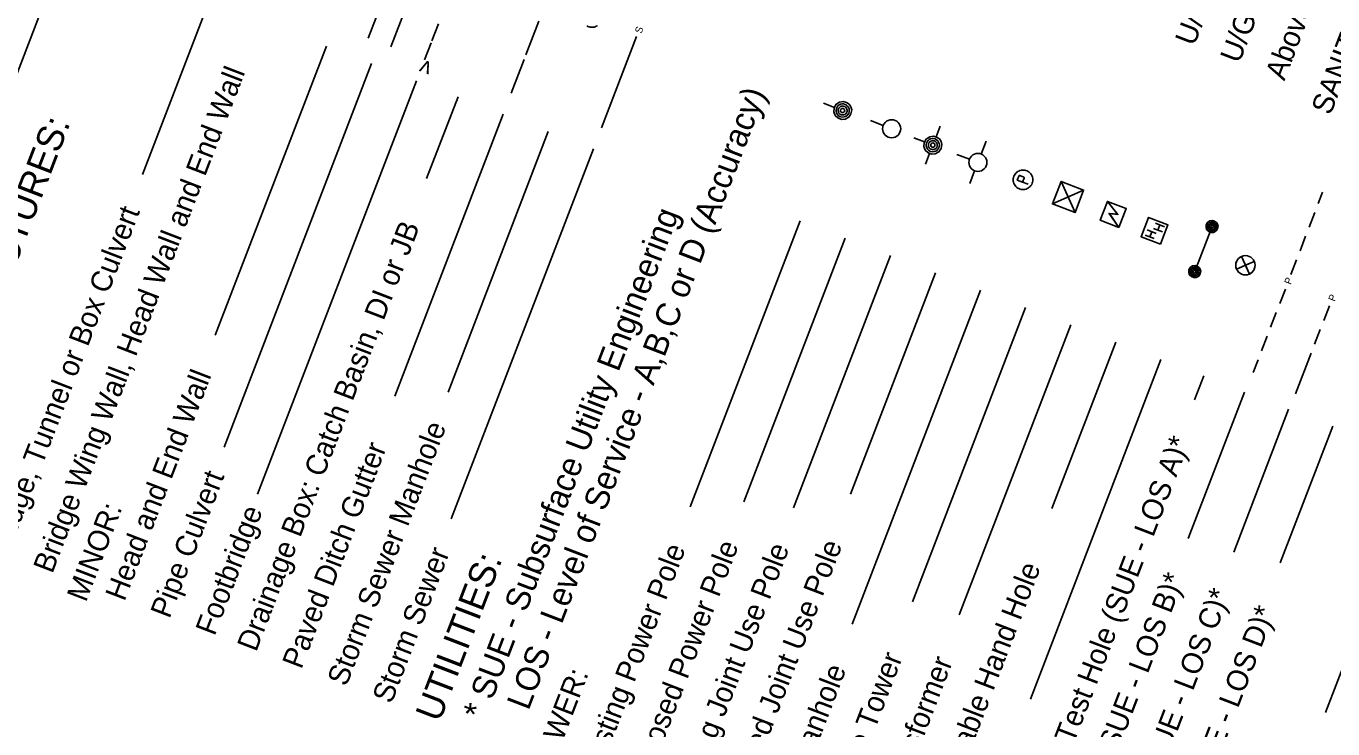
# Model space of a CAD drawing. Extents: x 1015221 to 1064345, y 619216 to 647967.
# Drawn here: x 1047324 to 1051569, y 630539 to 632823 of the extents above; entities that cross this region are included whole.
import ezdxf

# ---------------------------------------------------------------- set-up
doc = ezdxf.new("R2010")
doc.units = 0
doc.layers.add('Default', color=7, linetype='Continuous')

msp = doc.modelspace()

# ---------------------------------------------------------------- linework, layer by layer
at = {"layer": 'Default'}
for p, q in [((1048435, 632784.1), (1048667.1, 633388.3)), ((1048508.2, 632756), (1048740.4, 633360.2)), ((1047465.1, 633114.8), (1046888.4, 631613.8)), ((1047918.1, 632904.5), (1047701.5, 632340.8)), ((1048642, 632776), (1048663.1, 632830.9)), ((1048947.4, 632730.1), (1048989.6, 632840)), ((1049192.6, 632493), (1049306.6, 632789.8)), ((1048298.9, 632758.2), (1047937.9, 631818.5)), ((1048618.1, 632713.7), (1048639.2, 632768.7)), ((1048445.4, 632701.9), (1047966.5, 631455.4)), ((1048899.6, 632605.6), (1048941.8, 632715.4)), ((1048591.9, 632645.6), (1048075.6, 631301.8)), ((1048726.9, 632593.8), (1048624.8, 632327.9)), ((1049949.3, 632559.5), (1049914.1, 632573)), ((1048873.4, 632537.5), (1048521.1, 631620.6)), ((1050107.9, 632500.4), (1050066.7, 632516.2)), ((1049019.9, 632481.2), (1048694.4, 631634)), ((1050279.7, 632463.6), (1050293.2, 632498.7)), ((1050242.2, 632447), (1050207.1, 632460.5)), ((1050426.2, 632407.8), (1050442.1, 632449)), ((1049166.4, 632424.9), (1048704.3, 631222.3)), ((1050258.9, 632409.5), (1050245.4, 632374.4)), ((1050388.2, 632390.9), (1050347, 632406.7)), ((1050405.1, 632352.9), (1050389.3, 632311.7)), ((1050551.9, 632337.5), (1050564.5, 632332.7)), ((1050566, 632329.4), (1050560.8, 632316.1)), ((1050686.1, 632318.6), (1050731.2, 632217.3)), ((1050759.3, 632290.5), (1050658, 632245.5)), ((1051521.3, 632246.6), (1051535.6, 632284)), ((1049838.4, 632190.2), (1049481.4, 631261)), ((1050992.3, 632183), (1051021.8, 632171.6)), ((1051000.8, 632160.3), (1051007.3, 632177.2)), ((1051491.7, 632169.7), (1051510, 632217.3)), ((1049984.9, 632133.9), (1049655.7, 631277.1)), ((1050958.9, 632144.1), (1050988.4, 632132.8)), ((1050965.3, 632161), (1050994.9, 632149.6)), ((1050973.9, 632138.3), (1050980.4, 632155.2)), ((1050985.8, 632166.1), (1051015.3, 632154.8)), ((1051120.1, 632025.6), (1051176.3, 632172.1)), ((1051462.2, 632092.8), (1051480.5, 632140.4)), ((1050131.4, 632077.6), (1049816.5, 631257.9)), ((1051432.6, 632015.9), (1051450.9, 632063.5)), ((1050277.9, 632021.3), (1050001.4, 631301.9)), ((1050424.3, 631965), (1050007.4, 630879.9)), ((1051396.3, 631921.4), (1051414.6, 631969)), ((1050570.8, 631908.8), (1050203.1, 630951.7)), ((1051366.8, 631844.5), (1051385.1, 631892.1)), ((1051539.2, 631866.5), (1051557.5, 631914.1)), ((1050717.3, 631852.5), (1050355.3, 630910.3)), ((1051509.7, 631789.6), (1051528, 631837.2)), ((1050863.8, 631796.2), (1050655.9, 631255)), ((1051337.2, 631767.6), (1051355.5, 631815.2)), ((1051447.7, 631628.3), (1051498.4, 631760.3)), ((1051010.3, 631739.9), (1050586.2, 630636.2)), ((1051310.5, 631698), (1051326, 631738.3)), ((1051149.3, 631686.5), (1051119.3, 631608.6)), ((1051281.5, 631633.4), (1051098.9, 631157.9)), ((1051425.2, 631578.2), (1051246.9, 631114)), ((1051568.9, 631523), (1051398.1, 631078.5)), ((1051859.3, 631411.4), (1051544.5, 630591.9))]:
    msp.add_line(p, q, dxfattribs=at)
for points in [[(1049145.5, 632824.5), (1049148.9, 632822.7), (1049152.7, 632821.2), (1049156.5, 632820.3), (1049160.6, 632819.8), (1049164.4, 632819.7), (1049168.5, 632820.3), (1049172.2, 632821.4), (1049176, 632822.9), (1049179.5, 632824.8)], [(1049984, 632569.1), (1049978.9, 632570.5), (1049974, 632570.5), (1049969.2, 632569.3), (1049964.7, 632567.2), (1049961, 632564.3), (1049958.1, 632559.8), (1049955.9, 632555.7), (1049955.1, 632550.4), (1049955.1, 632545.5), (1049956.5, 632541.2), (1049959.1, 632536.5), (1049962, 632532.9), (1049966.5, 632529.9), (1049970.8, 632528.3), (1049976.1, 632527.5), (1049980.7, 632528.2), (1049985.7, 632530), (1049989.7, 632532.2), (1049993, 632535.9), (1049995.9, 632540.3), (1049997, 632544.9), (1049997.8, 632550.2), (1049997.1, 632554.8), (1049995.1, 632559.3), (1049992.4, 632563.4), (1049988.7, 632566.7), (1049984, 632569.1)], [(1049981.5, 632562.6), (1049977.5, 632563.6), (1049973.1, 632563.4), (1049969.4, 632561.7), (1049966, 632559.3), (1049963.6, 632556.5), (1049962, 632552.2), (1049961.8, 632548.5), (1049962.7, 632544.4), (1049964.4, 632540.7), (1049967.5, 632537.6), (1049971.1, 632535.6), (1049975.1, 632534.7), (1049979.5, 632534.9), (1049983.3, 632536.5), (1049986.7, 632538.9), (1049989, 632541.8), (1049990.7, 632546.1), (1049990.8, 632549.8), (1049989.9, 632553.8), (1049988.2, 632557.6), (1049985.1, 632560.6), (1049981.5, 632562.6)], [(1049978.8, 632555.6), (1049975.9, 632556.1), (1049973.1, 632555.3), (1049971.2, 632553.6), (1049969.6, 632551.1), (1049969.7, 632548), (1049970.5, 632545.2), (1049972.7, 632543.1), (1049974.9, 632542.2), (1049978, 632542.3), (1049980.5, 632543.8), (1049982.6, 632546.1), (1049983.1, 632549), (1049982.8, 632551.6), (1049981.3, 632554), (1049978.8, 632555.6)], [(1050277, 632456.6), (1050271.9, 632457.9), (1050267, 632457.9), (1050262.1, 632456.7), (1050257.6, 632454.7), (1050254, 632451.7), (1050251.1, 632447.3), (1050248.9, 632443.2), (1050248.1, 632437.9), (1050248, 632432.9), (1050249.5, 632428.7), (1050252, 632424), (1050255, 632420.3), (1050259.4, 632417.4), (1050263.8, 632415.7), (1050269, 632414.9), (1050273.7, 632415.7), (1050278.7, 632417.4), (1050282.6, 632419.6), (1050285.9, 632423.3), (1050288.9, 632427.8), (1050290, 632432.3), (1050290.8, 632437.6), (1050290.1, 632442.2), (1050288.1, 632446.7), (1050285.3, 632450.9), (1050281.6, 632454.2), (1050277, 632456.6)], [(1050274.5, 632450.1), (1050270.5, 632451), (1050266.1, 632450.8), (1050262.3, 632449.2), (1050258.9, 632446.8), (1050256.6, 632443.9), (1050254.9, 632439.6), (1050254.8, 632435.9), (1050255.7, 632431.9), (1050257.4, 632428.1), (1050260.5, 632425), (1050264.1, 632423.1), (1050268.1, 632422.1), (1050272.5, 632422.3), (1050276.2, 632424), (1050279.6, 632426.4), (1050282, 632429.2), (1050283.6, 632433.5), (1050283.8, 632437.2), (1050282.9, 632441.3), (1050281.2, 632445), (1050278.1, 632448.1), (1050274.5, 632450.1)], [(1050271.8, 632443.1), (1050268.9, 632443.6), (1050266.1, 632442.8), (1050264.2, 632441), (1050262.6, 632438.5), (1050262.6, 632435.4), (1050263.4, 632432.6), (1050265.7, 632430.5), (1050267.9, 632429.7), (1050271, 632429.7), (1050273.5, 632431.3), (1050275.6, 632433.5), (1050276.1, 632436.4), (1050275.8, 632439), (1050274.3, 632441.5), (1050271.8, 632443.1)], [(1050532.5, 632335.4), (1050531.3, 632331.5), (1050530.6, 632327.7), (1050530.5, 632323.7), (1050530.8, 632319.7), (1050531.6, 632315.9), (1050532.8, 632312.1), (1050534.7, 632308.4), (1050536.7, 632305.2), (1050539.3, 632302), (1050542.4, 632299.4), (1050545.6, 632297.1), (1050549, 632295.2), (1050552.8, 632293.8), (1050556.6, 632292.9), (1050560.7, 632292.4), (1050564.5, 632292.3), (1050568.6, 632292.9), (1050572.3, 632293.9), (1050576.1, 632295.5), (1050579.6, 632297.4), (1050582.7, 632299.8), (1050585.6, 632302.5), (1050588.2, 632305.6), (1050590.4, 632309.1), (1050592, 632312.6), (1050593.2, 632316.5), (1050593.9, 632320.3), (1050594.1, 632324.4), (1050593.7, 632328.3), (1050593, 632332.1), (1050591.7, 632335.9), (1050589.8, 632339.6), (1050587.8, 632342.9), (1050585.2, 632346), (1050582.1, 632348.6), (1050578.9, 632350.9), (1050575.5, 632352.8), (1050571.7, 632354.2), (1050567.9, 632355.1), (1050563.8, 632355.6), (1050560, 632355.7), (1050555.9, 632355.1), (1050552.2, 632354.1), (1050548.4, 632352.5), (1050544.9, 632350.6), (1050541.8, 632348.2), (1050538.9, 632345.6), (1050536.3, 632342.4), (1050534.1, 632338.9), (1050532.5, 632335.4)], [(1050578.5, 632309.3), (1050560.8, 632316.1), (1050543.5, 632322.8), (1050548.6, 632336.1)], [(1050548.6, 632336.1), (1050549.2, 632336.9), (1050550, 632337.5), (1050550.9, 632337.7), (1050551.9, 632337.5)], [(1050564.5, 632332.7), (1050565.4, 632332.1), (1050565.9, 632331.3), (1050566.1, 632330.5), (1050566, 632329.4)], [(1050759.3, 632290.5), (1050731.2, 632217.3), (1050658, 632245.5), (1050686.1, 632318.6), (1050759.3, 632290.5), (1050731.2, 632217.3), (1050658, 632245.5), (1050686.1, 632318.6), (1050759.3, 632290.5)], [(1050874, 632169.2), (1050897.5, 632230.2), (1050836.4, 632253.7), (1050813, 632192.7), (1050874, 632169.2)], [(1050874, 632169.2), (1050843.7, 632213.9), (1050868.9, 632212.3), (1050836.4, 632253.7)], [(1050874, 632169.2), (1050842.1, 632214.8), (1050870.5, 632211.4), (1050836.4, 632253.7)], [(1051009.1, 632114.4), (1051033.3, 632177.5), (1050970.2, 632201.7), (1050946, 632138.6), (1051009.1, 632114.4)], [(1051181.5, 632185.5), (1051178.1, 632186.4), (1051174.8, 632186.4), (1051171.6, 632185.5), (1051168.6, 632184.2), (1051166.2, 632182.3), (1051164.2, 632179.3), (1051162.7, 632176.5), (1051162.2, 632173), (1051162.2, 632169.7), (1051163.1, 632166.9), (1051164.8, 632163.7), (1051166.8, 632161.3), (1051169.8, 632159.3), (1051172.6, 632158.2), (1051176.2, 632157.7), (1051179.3, 632158.2), (1051182.6, 632159.4), (1051185.2, 632160.9), (1051187.4, 632163.3), (1051189.4, 632166.3), (1051190.1, 632169.3), (1051190.7, 632172.8), (1051190.2, 632175.9), (1051188.9, 632178.9), (1051187, 632181.7), (1051184.6, 632183.9), (1051181.5, 632185.5)], [(1051179.8, 632181.1), (1051177.1, 632181.8), (1051174.2, 632181.6), (1051171.7, 632180.5), (1051169.4, 632178.9), (1051167.9, 632177), (1051166.8, 632174.2), (1051166.7, 632171.7), (1051167.3, 632169), (1051168.4, 632166.5), (1051170.5, 632164.5), (1051172.9, 632163.1), (1051175.5, 632162.5), (1051178.5, 632162.6), (1051181, 632163.7), (1051183.2, 632165.3), (1051184.8, 632167.2), (1051185.9, 632170.1), (1051186, 632172.6), (1051185.4, 632175.3), (1051184.3, 632177.8), (1051182.2, 632179.8), (1051179.8, 632181.1)], [(1051178, 632176.5), (1051176.1, 632176.8), (1051174.2, 632176.3), (1051172.9, 632175.1), (1051171.9, 632173.4), (1051171.9, 632171.4), (1051172.4, 632169.5), (1051173.9, 632168.1), (1051175.4, 632167.5), (1051177.5, 632167.6), (1051179.1, 632168.6), (1051180.5, 632170.1), (1051180.9, 632172.1), (1051180.7, 632173.8), (1051179.7, 632175.4), (1051178, 632176.5)], [(1051272.1, 632074.8), (1051297.6, 632017.5), (1051284.8, 632046.2), (1051256.2, 632033.4), (1051313.5, 632058.9)], [(1051256.2, 632033.4), (1051284.8, 632046.2), (1051272.1, 632074.8)], [(1051313.5, 632058.9), (1051284.8, 632046.2), (1051297.6, 632017.5)], [(1051125.2, 632039), (1051121.8, 632039.9), (1051118.5, 632039.9), (1051115.3, 632039.1), (1051112.3, 632037.7), (1051109.9, 632035.8), (1051107.9, 632032.8), (1051106.4, 632030), (1051105.9, 632026.5), (1051105.9, 632023.2), (1051106.9, 632020.4), (1051108.6, 632017.3), (1051110.5, 632014.8), (1051113.5, 632012.9), (1051116.4, 632011.8), (1051119.9, 632011.2), (1051123, 632011.7), (1051126.3, 632012.9), (1051129, 632014.4), (1051131.1, 632016.8), (1051133.1, 632019.8), (1051133.9, 632022.8), (1051134.4, 632026.3), (1051133.9, 632029.4), (1051132.6, 632032.4), (1051130.7, 632035.2), (1051128.3, 632037.4), (1051125.2, 632039)], [(1051123.5, 632034.7), (1051120.9, 632035.3), (1051117.9, 632035.2), (1051115.4, 632034), (1051113.1, 632032.4), (1051111.6, 632030.6), (1051110.5, 632027.7), (1051110.4, 632025.2), (1051111, 632022.5), (1051112.1, 632020), (1051114.2, 632018), (1051116.6, 632016.6), (1051119.3, 632016), (1051122.2, 632016.1), (1051124.7, 632017.3), (1051127, 632018.9), (1051128.5, 632020.7), (1051129.6, 632023.6), (1051129.7, 632026.1), (1051129.1, 632028.8), (1051128, 632031.3), (1051125.9, 632033.3), (1051123.5, 632034.7)], [(1051121.7, 632030), (1051119.8, 632030.3), (1051117.9, 632029.8), (1051116.6, 632028.6), (1051115.6, 632027), (1051115.6, 632024.9), (1051116.1, 632023), (1051117.7, 632021.6), (1051119.1, 632021), (1051121.2, 632021.1), (1051122.8, 632022.1), (1051124.2, 632023.6), (1051124.6, 632025.6), (1051124.4, 632027.3), (1051123.4, 632028.9), (1051121.7, 632030)]]:
    msp.add_lwpolyline(points, dxfattribs=at)
for points in [[(1050003.4, 632538.7), (1050005.6, 632550.9), (1050003.1, 632560.6), (1049997.8, 632569.4), (1049988.3, 632575.5), (1049978.2, 632578.2), (1049966.4, 632576.5), (1049954.1, 632568.8), (1049948.2, 632556.8), (1049947.3, 632544.8), (1049951.6, 632533.2), (1049960.2, 632524.9), (1049972.1, 632520.4), (1049984, 632520.7), (1049995.9, 632527.3)], [(1050296.3, 632426.2), (1050298.5, 632438.4), (1050296, 632448), (1050290.7, 632456.9), (1050281.3, 632463), (1050271.1, 632465.6), (1050259.3, 632464), (1050247.1, 632456.3), (1050241.2, 632444.3), (1050240.3, 632432.2), (1050244.6, 632420.6), (1050253.2, 632412.4), (1050265.1, 632407.8), (1050277, 632408.2), (1050288.9, 632414.8)], [(1051194.4, 632165.2), (1051195.8, 632173.3), (1051194.2, 632179.8), (1051190.6, 632185.7), (1051184.3, 632189.7), (1051177.6, 632191.5), (1051169.7, 632190.4), (1051161.5, 632185.3), (1051157.6, 632177.3), (1051157, 632169.2), (1051159.8, 632161.5), (1051165.6, 632156), (1051173.5, 632153), (1051181.5, 632153.2), (1051189.4, 632157.6)], [(1051138.1, 632018.7), (1051139.5, 632026.8), (1051137.9, 632033.3), (1051134.3, 632039.2), (1051128.1, 632043.3), (1051121.3, 632045), (1051113.4, 632043.9), (1051105.2, 632038.8), (1051101.3, 632030.8), (1051100.7, 632022.7), (1051103.6, 632015), (1051109.3, 632009.5), (1051117.2, 632006.5), (1051125.2, 632006.7), (1051133.1, 632011.1)]]:
    msp.add_lwpolyline(points, close=True, dxfattribs=at)
for centre, radius in [((1050135.4, 632489.8), 29.4), ((1050415.8, 632380.3), 29.4), ((1051284.8, 632046.2), 31.4)]:
    msp.add_circle(centre, radius, dxfattribs=at)
for start, end in [(113.983, 203.983), (293.983, 23.983)]:
    msp.add_arc((1051284.8, 632046.2), 31.4, start, end, dxfattribs=at)

# ---------------------------------------------------------------- texts
for s, height, rotation, p in [('U/G Gas Line (SUE - LOS C)*', 68.654, 68.983, (1051118.3, 632756)), ('U/G Gas Line (SUE - LOS D)*', 68.654, 68.983, (1051264.8, 632699.7)), ('Above Ground Gas Line', 68.654, 68.983, (1051411.3, 632643.4)), ('SANITARY SEWER:', 68.654, 68.983, (1051561, 632531.1)), ('S', 23.5, 68.983, (1049322.1, 632797.3)), ('Bridge Wing Wall, Head Wall and End Wall', 68.654, 68.983, (1047408.6, 631041.3)), ('v', 51.8, 158.7422, (1048645.4, 632703.1)), ('LOS - Level of Service - A,B,C or D (Accuracy) ', 77.677, 68.983, (1048955.7, 630596.5)), ('EXISTING STRUCTURES:', 86.308, 68.983, (1046969.2, 631210.1)), ('Bridge, Tunnel or Box Culvert', 68.654, 68.983, (1047262.1, 631097.5)), ('* SUE - Subsurface Utility Engineering', 77.677, 68.983, (1048812.8, 630565.1)), ('Drainage Box: Catch Basin, DI or JB', 68.654, 68.983, (1048070.9, 630786.9)), ('P', 23.5, 68.983, (1051432.1, 631981.6)), ('P', 23.5, 68.983, (1051575, 631926.7)), ('Head and End Wall', 68.654, 68.983, (1047642.9, 630951.2)), ('Storm Sewer Manhole', 68.654, 68.983, (1048363.9, 630674.3)), ('Paved Ditch Gutter', 68.654, 68.983, (1048217.5, 630730.6)), ('U/G Power Line Test Hole (SUE - LOS A)*', 68.654, 68.983, (1050485.4, 629859.5)), ('Pipe Culvert', 68.654, 68.983, (1047789.3, 630895)), ('MINOR:', 68.65, 68.983, (1047517.9, 630948.6)), ('Footbridge', 68.65, 68.983, (1047935.8, 630838.8)), ('Storm Sewer', 68.654, 68.983, (1048510.4, 630618)), ('Existing Power Pole', 68.654, 68.983, (1049174.5, 630362.9)), ('Proposed Power Pole', 68.654, 68.983, (1049321, 630306.6)), ('Existing Joint Use Pole', 68.654, 68.983, (1049467.4, 630250.4)), ('Proposed Joint Use Pole', 68.654, 68.983, (1049614, 630194.2)), ('UTILITIES:', 86.31, 68.983, (1048666.9, 630557.8)), ('U/G Power Cable Hand Hole', 68.654, 68.983, (1050200, 629969.1)), ('U/G Power Line (SUE - LOS B)*', 68.654, 68.983, (1050617.7, 629806.3)), ('U/G Power Line (SUE - LOS C)*', 68.654, 68.983, (1050764.4, 629750.2)), ('U/G Power Line (SUE - LOS D)*', 68.654, 68.983, (1050911, 629694.1)), ('Power Line Tower', 68.654, 68.983, (1049906.9, 630081.6)), ('Power Transformer', 68.654, 68.983, (1050053.3, 630025.3)), ('Power Manhole', 68.654, 68.983, (1049760.5, 630137.9)), ('POWER:', 68.65, 68.983, (1049018.4, 630372.1))]:
    msp.add_text(s, height=height, rotation=rotation, dxfattribs=at).set_placement(p)

doc.saveas('drawing.dxf')
